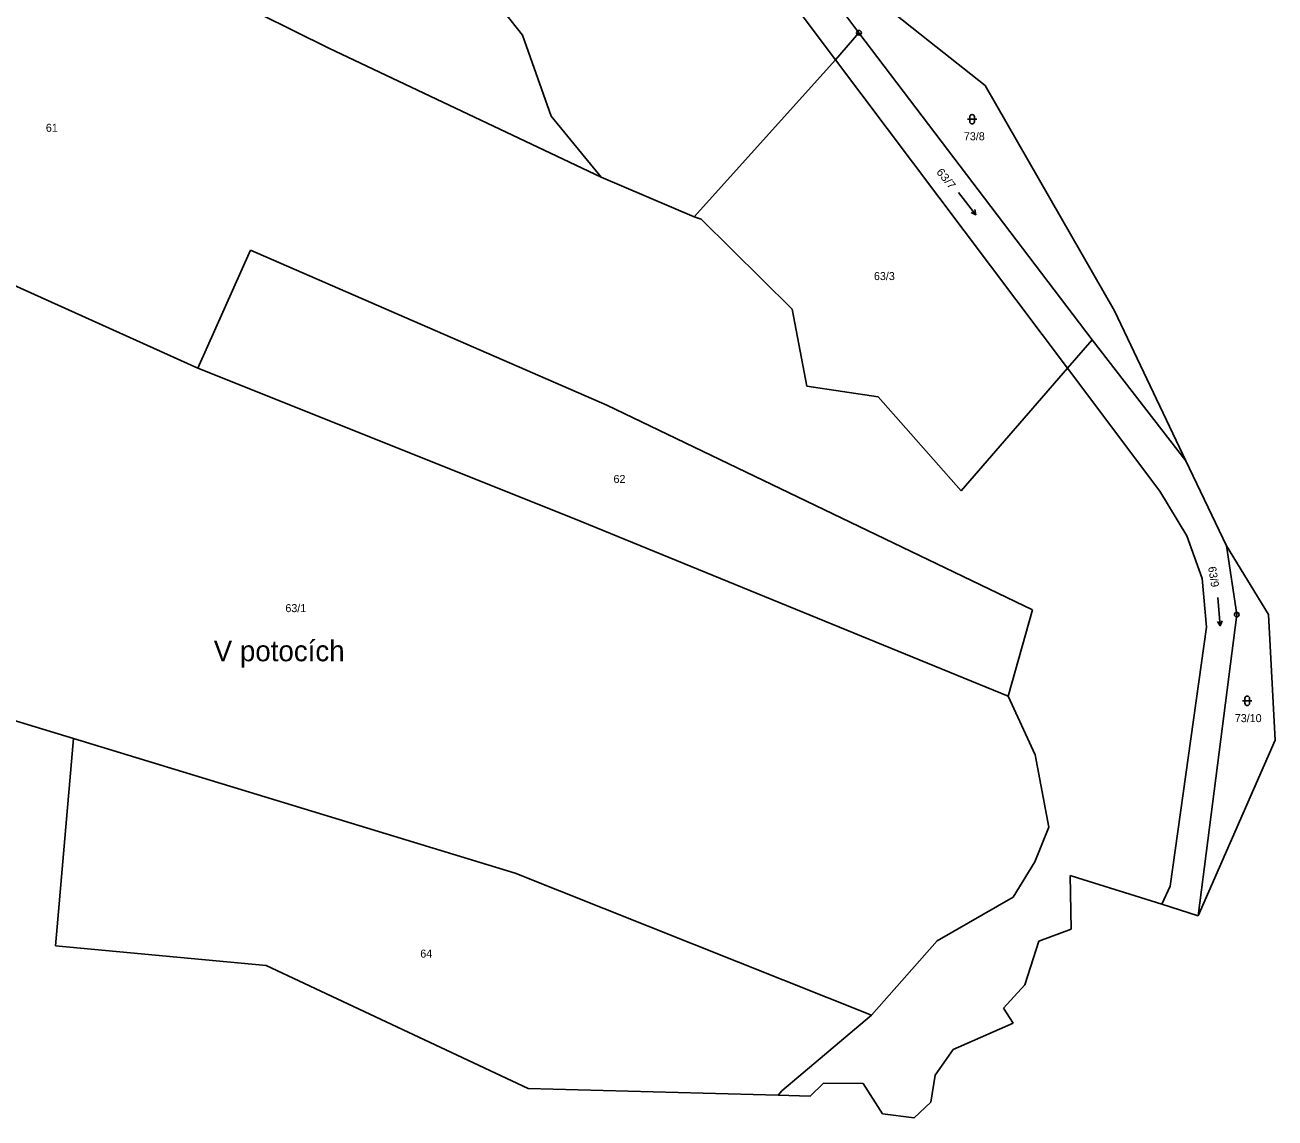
# Model space of a CAD drawing. Extents: x -791548 to -789311, y -1142631 to -1140855.
# Drawn here: x -789576.6 to -789311.1, y -1142631.3 to -1142399.2 of the extents above; entities that cross this region are included whole.
import ezdxf
from ezdxf.enums import TextEntityAlignment as Align

# ---------------------------------------------------------------- set-up
doc = ezdxf.new("R2010")
doc.units = 0
doc.header["$LTSCALE"] = 0.68
for name, color, linetype, lineweight in [('1', 7, 'Continuous', 25), ('3', 7, 'Continuous', 25), ('7', 7, 'Continuous', 13), ('8', 7, 'Continuous', 25)]:
    doc.layers.add(name, color=color, linetype=linetype, lineweight=lineweight)
doc.layers.add('2', color=7, linetype='Continuous')

msp = doc.modelspace()

# ---------------------------------------------------------------- linework, layer by layer
at = {"layer": '1'}
for p, q in [((-789404.46, -1142406.59), (-789463.16, -1142328.26)), ((-789492.74, -1142373.77), (-789470.94, -1142401.32)), ((-789419.67, -1142373.91), (-789399.48, -1142400.85)), ((-789512.08, -1142404.14), (-789555.5, -1142382.48)), ((-789394.07, -1142395.09), (-789384.49, -1142402.67)), ((-789464.86, -1142418.52), (-789470.94, -1142401.32)), ((-789399.48, -1142400.85), (-789404.46, -1142406.59)), ((-789399.48, -1142400.85), (-789349.96, -1142466.04)), ((-789384.49, -1142402.67), (-789372.68, -1142412.02)), ((-789454.21, -1142431.5), (-789512.08, -1142404.14)), ((-789404.46, -1142406.59), (-789434.47, -1142439.89)), ((-789355.2, -1142472.09), (-789404.46, -1142406.59)), ((-789345.21, -1142459.91), (-789372.68, -1142412.02)), ((-789454.21, -1142431.5), (-789464.86, -1142418.52)), ((-789539.89, -1142472.06), (-789638.91, -1142427.38)), ((-789434.47, -1142439.89), (-789454.21, -1142431.5)), ((-789434.47, -1142439.89), (-789432.99, -1142440.43)), ((-789432.99, -1142440.43), (-789413.64, -1142459.52)), ((-789528.71, -1142446.97), (-789539.89, -1142472.06)), ((-789453.02, -1142479.93), (-789528.71, -1142446.97)), ((-789413.64, -1142459.52), (-789410.57, -1142475.86)), ((-789330.09, -1142491.71), (-789345.21, -1142459.91)), ((-789355.2, -1142472.09), (-789349.96, -1142466.04)), ((-789349.96, -1142466.04), (-789330.09, -1142491.71)), ((-789460.01, -1142503.95), (-789539.89, -1142472.06)), ((-789377.79, -1142498.11), (-789355.2, -1142472.09)), ((-789335.62, -1142498.16), (-789355.2, -1142472.09)), ((-789410.57, -1142475.86), (-789395.38, -1142478.13)), ((-789395.38, -1142478.13), (-789377.79, -1142498.11)), ((-789362.6, -1142523.37), (-789453.02, -1142479.93)), ((-789321.41, -1142509.78), (-789330.09, -1142491.71)), ((-789329.87, -1142507.68), (-789335.62, -1142498.16)), ((-789367.8, -1142541.68), (-789460.01, -1142503.95)), ((-789326.58, -1142516.71), (-789329.87, -1142507.68)), ((-789321.41, -1142509.78), (-789319.26, -1142524.39)), ((-789321.41, -1142509.78), (-789312.53, -1142524.37)), ((-789325.67, -1142527.04), (-789326.58, -1142516.71)), ((-789367.8, -1142541.68), (-789362.6, -1142523.37)), ((-789319.26, -1142524.39), (-789327.46, -1142588.31)), ((-789311.13, -1142551.01), (-789312.53, -1142524.37)), ((-789333.38, -1142582.05), (-789325.67, -1142527.04)), ((-789600.44, -1142540.39), (-789566.28, -1142550.67)), ((-789362.09, -1142554.16), (-789367.8, -1142541.68)), ((-789569.75, -1142590.7), (-789566.28, -1142550.67)), ((-789472.52, -1142579.31), (-789566.28, -1142550.67)), ((-789327.46, -1142588.31), (-789311.13, -1142551.01)), ((-789359.18, -1142569.53), (-789362.09, -1142554.16)), ((-789362.12, -1142576.91), (-789359.18, -1142569.53)), ((-789366.73, -1142584.36), (-789362.12, -1142576.91)), ((-789396.79, -1142609.44), (-789472.52, -1142579.31)), ((-789354.43, -1142591.14), (-789354.6, -1142579.76)), ((-789353.05, -1142580.25), (-789354.6, -1142579.76)), ((-789335.15, -1142585.89), (-789353.05, -1142580.25)), ((-789335.15, -1142585.89), (-789333.38, -1142582.05)), ((-789382.89, -1142593.65), (-789366.73, -1142584.36)), ((-789327.46, -1142588.31), (-789335.15, -1142585.89)), ((-789569.75, -1142590.7), (-789570.1, -1142594.73)), ((-789361.26, -1142593.75), (-789354.43, -1142591.14)), ((-789396.79, -1142609.44), (-789382.89, -1142593.65)), ((-789364.28, -1142602.99), (-789361.26, -1142593.75)), ((-789570.1, -1142594.73), (-789525.35, -1142598.91)), ((-789525.35, -1142598.91), (-789469.74, -1142625)), ((-789368.76, -1142607.97), (-789364.28, -1142602.99)), ((-789415.89, -1142625.47), (-789396.79, -1142609.44)), ((-789366.77, -1142611.1), (-789368.76, -1142607.97)), ((-789379.51, -1142616.73), (-789366.77, -1142611.1)), ((-789383.3, -1142622.16), (-789379.51, -1142616.73)), ((-789384.2, -1142627.91), (-789383.3, -1142622.16)), ((-789469.74, -1142625), (-789416.64, -1142626.42)), ((-789415.89, -1142625.47), (-789416.64, -1142626.42)), ((-789407.02, -1142623.84), (-789409.86, -1142626.6)), ((-789407.02, -1142623.84), (-789398.61, -1142623.92)), ((-789398.61, -1142623.92), (-789394.51, -1142630.41)), ((-789416.64, -1142626.42), (-789409.86, -1142626.6)), ((-789387.79, -1142631.27), (-789384.2, -1142627.91)), ((-789394.51, -1142630.41), (-789387.79, -1142631.27))]:
    msp.add_line(p, q, dxfattribs=at)
at = {"layer": '3'}
for p, q in [((-789376.451, -1142419.201), (-789374.449, -1142419.201)), ((-789375.951, -1142418.701), (-789375.951, -1142419.702)), ((-789374.949, -1142419.702), (-789374.949, -1142418.701)), ((-789374.689, -1142439.473), (-789375.686, -1142439.012)), ((-789322.766, -1142526.746), (-789323.35, -1142525.817)), ((-789318.031, -1142542.691), (-789316.029, -1142542.691)), ((-789317.531, -1142542.191), (-789317.531, -1142543.192)), ((-789316.529, -1142543.192), (-789316.529, -1142542.191))]:
    msp.add_line(p, q, dxfattribs=at)
for points in [[(-789378.383, -1142434.745), (-789374.689, -1142439.473), (-789374.896, -1142438.394)], [(-789323.289, -1142520.769), (-789322.766, -1142526.746), (-789322.351, -1142525.729)]]:
    msp.add_lwpolyline(points, dxfattribs=at)
for centre, start, end in [((-789375.45, -1142418.7009), 0, 180), ((-789375.45, -1142419.7009), 180, 359.98789), ((-789317.03, -1142542.1909), 0, 180), ((-789317.03, -1142543.1909), 180, 359.98789)]:
    msp.add_arc(centre, 0.5, start, end, dxfattribs=at)
at = {"layer": '8'}
for centre, radius in [((-789399.48, -1142400.8499), 0.5), ((-789399.48, -1142400.8499), 0.0303), ((-789319.26, -1142524.3899), 0.5), ((-789319.26, -1142524.3899), 0.0303)]:
    msp.add_circle(centre, radius, dxfattribs=at)

# ---------------------------------------------------------------- texts
at = {"layer": '2'}
for s, p in [('61', (-789570.909, -1142421.862)), ('73/8', (-789374.989, -1142423.665)), ('63/3', (-789394.089, -1142453.352)), ('62', (-789450.349, -1142496.432)), ('63/1', (-789519.089, -1142523.862)), ('73/10', (-789316.82, -1142547.215)), ('64', (-789491.389, -1142597.212))]:
    msp.add_text(s, height=1.7, dxfattribs=at).set_placement(p, align=Align.CENTER)
at = {"layer": '2', "width": 1.1}
msp.add_text('63/7', height=1.7, rotation=309, dxfattribs=at).set_placement((-789381.6367, -1142432.3391), align=Align.CENTER)
at = {"layer": '2'}
msp.add_text('63/9', height=1.7, rotation=279, dxfattribs=at).set_placement((-789324.9963, -1142516.478), align=Align.CENTER)
at = {"layer": '7'}
msp.add_text('V potocích', height=4.4, dxfattribs=at).set_placement((-789536.52, -1142534.29))

doc.saveas('drawing.dxf')
